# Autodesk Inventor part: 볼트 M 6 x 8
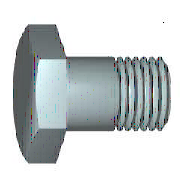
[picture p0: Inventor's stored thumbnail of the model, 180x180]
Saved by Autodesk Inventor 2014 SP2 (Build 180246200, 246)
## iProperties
Created: 2012-02
Part Number: 볼트 M 6 x 8
Material: 강철, 연강
Description: 6각 머리 볼트 및 6각 머리 나사
Document SubType Name: Modeling
Standard: KS B 1002
Designer: mduedu
Standards Organization: KS
Language: ko-KR
Size Designation: C  M 6 x 12
Categories: <MemberInstance><Categories><Category DisplayName="조임쇠" InternalName="e4da775c-781d-43d5-af7c-5136215cf5a6" Mnemonic="FSTN"><Category DisplayName="볼트" InternalN
Density: 1 g/cm^3
Appearance: 강철
IsCustomPart: 1
Author: mduedu
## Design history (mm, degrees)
sketch "스케치1"
  geometry: L1 (0, 3)-(8, 3); L2 (8, 3)-(8, 0); L3 (8, 0)-(0, 0); L4 (-2.4, 0)-(14.4, 0) reference; L5 (0, -0.6)-(0, 3.6) reference; L6 (0, 3)-(0, 0)
  constraints: 8 end point, 3 point on line, 1 collinear
  dimensions: "d2" = 6 diameter of L1 L3 (= GD); "d59" = 8 distance between parallel lines of L2 L5 (= NLG)
revolve "본체" sketch "스케치1" stored, may be unused: angle "d12" = 90 deg
sketch "스케치2"
  geometry: L1 (0, 5.774)-(5, 2.887); L2 (5, 2.887)-(5, -2.887); L3 (5, -2.887)-(0, -5.774); L4 (0, -5.774)-(-5, -2.887); L5 (-5, -2.887)-(-5, 2.887); L6 (-5, 2.887)-(0, 5.774); L7 (-7, 0)-(7, 0) reference; L8 (0, 8.083)-(0, -8.083) reference; 2 further points
  constraints: 12 end point, 2 midpoint, 1 coincident, 1 vertical, 11 other
  dimensions: "d11" = 10 distance between parallel lines of L5 L2 (= SW)
extrude "머리" join sketch "스케치2" distance "d3" = 4 (= KOH); taper "d4" = 0 deg
revolve "모따기1" stored, may be unused: angle "d21" = 90 deg
workplane "Work Plane1"
body "Solid1"
feature "스레드" dims "d15" = 9 (= GEL), "d16" = 0
chamfer "모따기2" distance "d6" = 0.61345 (= -0.5 x SPD + 0.5 x GD); stored, may be unused: second distance "d7" = 0.61355 (computed from GUL), angle "d55" = 45 deg
sketch "스케치4"
  geometry: L1 (-3.423, 6)-(-4, 5); L2 (-1.1, 0)-(-0.234, 0); L3 (-4.753, 0)-(0.519, 0) reference; L4 (-4, 6)-(-3.423, 6); L5 (-4, 5)-(-4, 6); L6 (0, 7.2)-(0, -1.2) reference
  constraints: 8 end point, 1 parallel, 1 perpendicular, 1 point on line
  dimensions: "d65" = 10 diameter of L1.end L2 (= SW); "d67" = 30 deg angle of L1 L5 (= ANG1); "d68" = 12 diameter of L4 L2 (= 1.2 x SW); "d69" = 4 distance between parallel lines of L5 L6 (= KOH)
other parameters: "NLG" = 8 [user parameter; used in 1 equation term], "GD" = 6 (= NND) [user parameter; used in 2 equation terms], "BDM" = 6 (= NND) [user parameter], "KOH" = 4 [user parameter; used in 2 equation terms], "GEL" = 9 [user parameter; used in 1 equation term], "SW" = 10 [user parameter; used in 5 equation terms], "SPD" = 4.7731 (= NND - 1.2269 x PTC) [user parameter; used in 1 equation term], "SD2" = 6 (= NND) [user parameter], "SD" = 0 [user parameter], "ANG1" = 30 deg [user parameter; used in 1 equation term], "GAL" = 0.61345 (= 0.61345 x PTC) [user parameter], "GUL" = 0.61345 (= 0.61345 x PTC) [user parameter; used in 1 equation term], "d8" = 0, "RR" = 0.25 [user parameter], "d58" = 0, "RR1" = 0.1 [user parameter], "GD1" = 4.7731 (= THREADDIA - 1.2269 x PTC) [user parameter], "THREADDIA" = 6 [user parameter; used in 1 equation term], "TOA" = 30 deg [user parameter], "PTC" = 1 [user parameter; used in 5 equation terms], "NND" = 6 [user parameter; used in 4 equation terms], "E0" = 11.55 (= 1.155 x SW) [user parameter]
